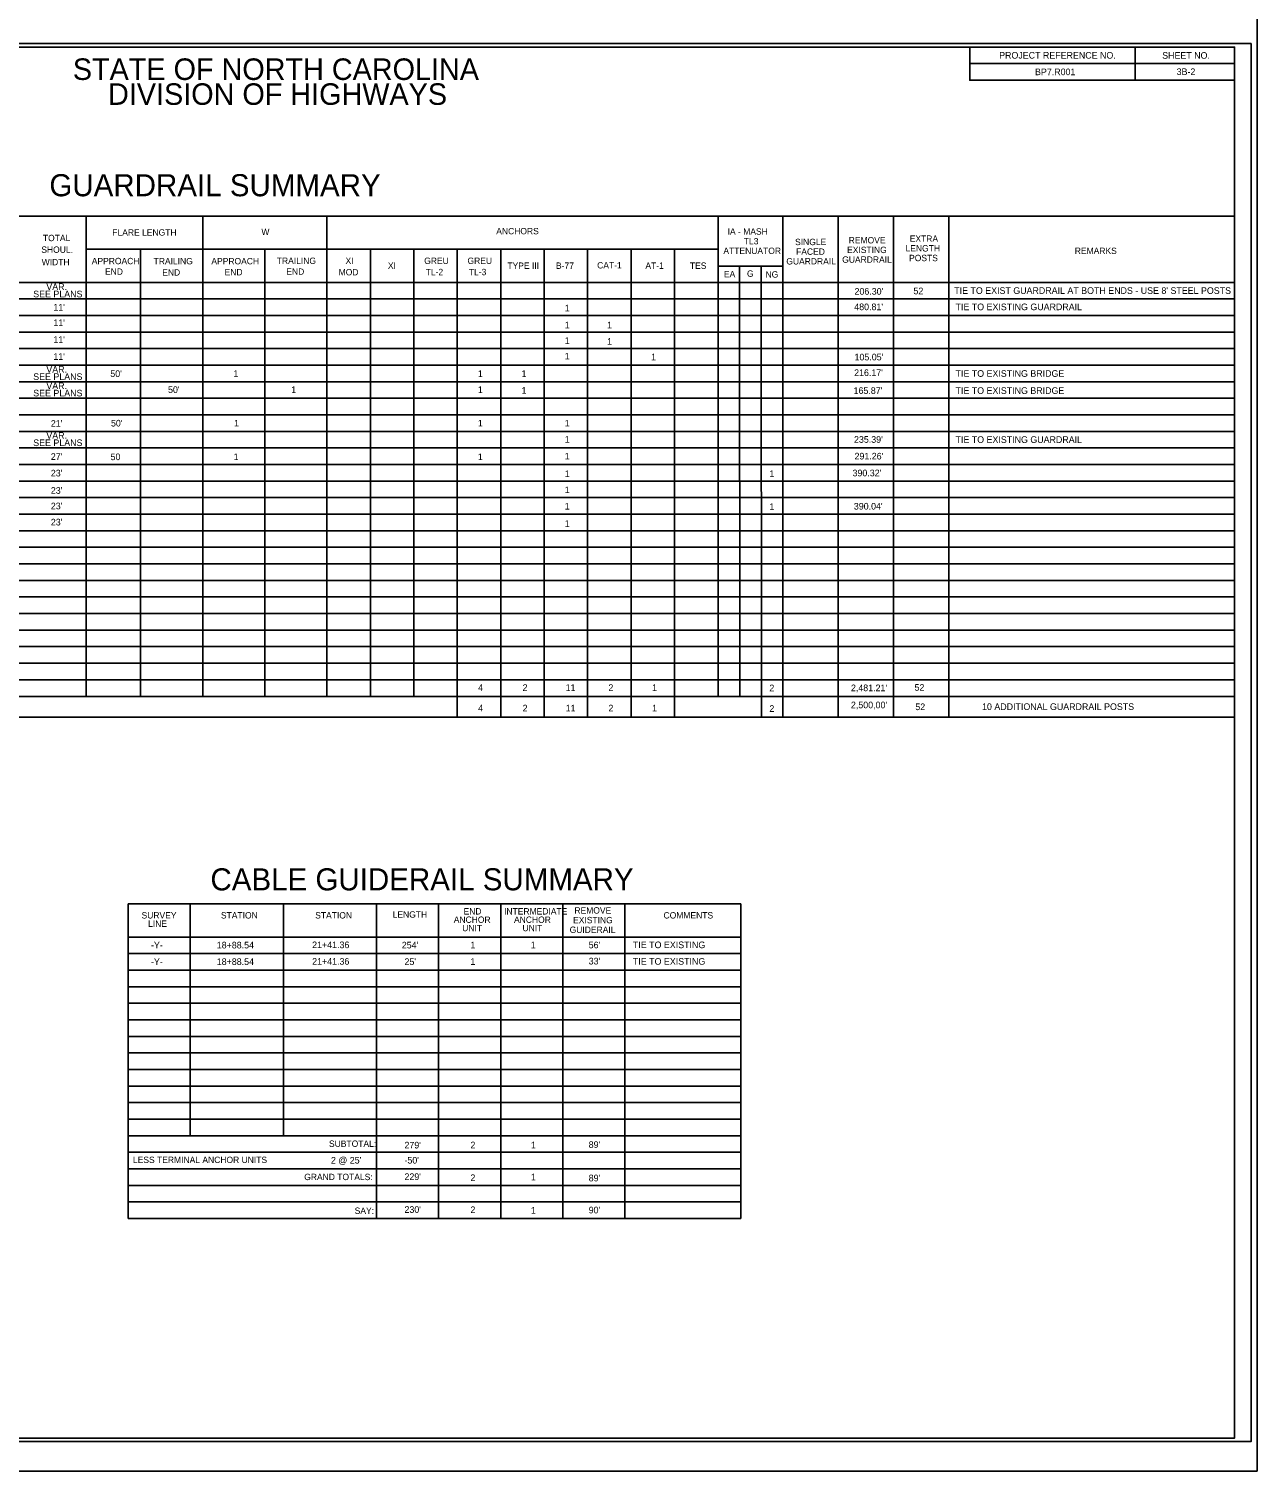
# Model space of a CAD drawing. Extents: x 1730642 to 1732326, y 538795 to 540995.
# Drawn here: x 1731398 to 1732326, y 538795 to 539884 of the extents above; entities that cross this region are included whole.
import ezdxf

# ---------------------------------------------------------------- set-up
doc = ezdxf.new("R2010")
doc.units = 0
for name, color, linetype in [('Default', 7, 'Continuous'), ('Old_Level_40', 7, 'Continuous'), ('Old_Level_44', 7, 'Continuous'), ('Sheet Cutting Line CELL', 7, 'Continuous'), ('Sheet Data Field CELL', 7, 'Continuous'), ('Sheet Pipe Summary CELL', 7, 'Continuous'), ('Sheet Pipe Summary Grid CELL', 7, 'Continuous'), ('Sheet Summary Combination CELL', 7, 'Continuous'), ('Sheet Summary Earthwork CELL', 7, 'Continuous')]:
    doc.layers.add(name, color=color, linetype=linetype)

msp = doc.modelspace()

# ---------------------------------------------------------------- linework, layer by layer
at = {"layer": 'Old_Level_40'}
for p, q in [((1732233.5, 539870.4), (1732233.5, 539845.4)), ((1732108.5, 539857.9), (1732308.5, 539857.9)), ((1732108.5, 539845.4), (1732308.5, 539845.4)), ((1731614.3, 539223.6), (1731614.3, 539223.6)), ((1731620.6, 539223.5), (1731620.6, 539223.5)), ((1731629.6, 539223.7), (1731629.6, 539223.7)), ((1731635.2, 539223.6), (1731635.2, 539223.6))]:
    msp.add_line(p, q, dxfattribs=at)
for points in [[(1732308.5, 539870.4), (1730808.5, 539870.4), (1730808.5, 538820.4), (1732308.5, 538820.4)], [(1732108.5, 539870.4), (1732308.5, 539870.4), (1732308.5, 539845.4), (1732108.5, 539845.4)]]:
    msp.add_lwpolyline(points, close=True, dxfattribs=at)
at = {"layer": 'Old_Level_44'}
for p, q in [((1730808.5, 539742.8), (1732308.5, 539742.8)), ((1731441.3, 539742.8), (1731441.3, 539380.3)), ((1731529.4, 539742.8), (1731529.4, 539380.3)), ((1731623.2, 539742.8), (1731623.2, 539380.3)), ((1731918.5, 539742.8), (1731918.5, 539380.3)), ((1731967.3, 539742.8), (1731967.3, 539364.7)), ((1732009.1, 539742.8), (1732009.1, 539364.7)), ((1732050.9, 539742.8), (1732050.9, 539364.7)), ((1732092.8, 539742.8), (1732092.8, 539364.7)), ((1731918.5, 539717.8), (1731441.3, 539717.8)), ((1731482.5, 539717.8), (1731482.5, 539380.3)), ((1731576.3, 539717.8), (1731576.3, 539380.3)), ((1731656, 539717.8), (1731656, 539380.3)), ((1731688.8, 539717.8), (1731688.8, 539380.3)), ((1731721.6, 539717.8), (1731721.6, 539364.7)), ((1731754.4, 539717.8), (1731754.4, 539364.7)), ((1731787.2, 539717.8), (1731787.2, 539364.7)), ((1731820, 539717.8), (1731820, 539364.7)), ((1731852.9, 539717.8), (1731852.9, 539364.7)), ((1731885.7, 539717.8), (1731885.7, 539364.7)), ((1731918.5, 539705), (1731967.1, 539705)), ((1731934.7, 539705), (1731934.9, 539380.3)), ((1731951.1, 539705), (1731951.3, 539364.7)), ((1730808.5, 539692.8), (1732308.5, 539692.8)), ((1730808.5, 539680.3), (1732308.5, 539680.3)), ((1730808.5, 539667.8), (1732308.5, 539667.8)), ((1730808.5, 539655.3), (1732308.5, 539655.3)), ((1730808.5, 539642.8), (1732308.5, 539642.8)), ((1730808.5, 539630.3), (1732308.5, 539630.3)), ((1730808.5, 539617.8), (1732308.5, 539617.8)), ((1730808.5, 539605.3), (1732308.5, 539605.3)), ((1730808.5, 539592.8), (1732308.5, 539592.8)), ((1730808.5, 539580.3), (1732308.5, 539580.3)), ((1730808.5, 539567.8), (1732308.5, 539567.8)), ((1730808.5, 539555.3), (1732308.5, 539555.3)), ((1730808.5, 539542.8), (1732308.5, 539542.8)), ((1730808.5, 539530.3), (1732308.5, 539530.3)), ((1730808.5, 539517.8), (1732308.5, 539517.8)), ((1730808.5, 539505.3), (1732308.5, 539505.3)), ((1730808.5, 539492.8), (1732308.5, 539492.8)), ((1730808.5, 539480.3), (1732308.5, 539480.3)), ((1730808.5, 539467.8), (1732308.5, 539467.8)), ((1730808.5, 539455.3), (1732308.5, 539455.3)), ((1730808.5, 539442.8), (1732308.5, 539442.8)), ((1730808.5, 539430.3), (1732308.5, 539430.3)), ((1730808.5, 539417.8), (1732308.5, 539417.8)), ((1730808.5, 539405.3), (1732308.5, 539405.3)), ((1730808.5, 539392.8), (1732308.5, 539392.8)), ((1730808.5, 539380.3), (1732308.5, 539380.3)), ((1730808.5, 539364.7), (1732308.5, 539364.7)), ((1731473.1, 539223.6), (1731935.7, 539223.6)), ((1731473.1, 539223.6), (1731473.1, 538986.1)), ((1731520, 539223.6), (1731520, 539048.6)), ((1731590.3, 539223.6), (1731590.3, 539048.6)), ((1731660.6, 539223.6), (1731660.6, 538986.1)), ((1731707.5, 539223.6), (1731707.5, 538986.1)), ((1731754.4, 539223.6), (1731754.4, 538986.1)), ((1731801.3, 539223.6), (1731801.3, 538986.1)), ((1731848.2, 539223.6), (1731848.2, 538986.1)), ((1731935.7, 539223.6), (1731935.7, 538986.1)), ((1731473.1, 539198.6), (1731935.7, 539198.6)), ((1731473.1, 539186.1), (1731935.7, 539186.1)), ((1731473.1, 539173.6), (1731935.7, 539173.6)), ((1731473.1, 539161.1), (1731935.7, 539161.1)), ((1731473.1, 539148.6), (1731935.7, 539148.6)), ((1731473.1, 539136.1), (1731935.7, 539136.1)), ((1731473.1, 539123.6), (1731935.7, 539123.6)), ((1731473.1, 539111.1), (1731935.7, 539111.1)), ((1731473.1, 539098.6), (1731935.7, 539098.6)), ((1731473.1, 539086.1), (1731935.7, 539086.1)), ((1731473.1, 539073.6), (1731935.7, 539073.6)), ((1731473.1, 539061.1), (1731935.7, 539061.1)), ((1731473.1, 539048.6), (1731935.7, 539048.6)), ((1731473.1, 539036.1), (1731935.7, 539036.1)), ((1731473.1, 539023.6), (1731935.7, 539023.6)), ((1731473.1, 539011.1), (1731935.7, 539011.1)), ((1731473.1, 538998.6), (1731935.7, 538998.6)), ((1731473.1, 538986.1), (1731935.7, 538986.1))]:
    msp.add_line(p, q, dxfattribs=at)
at = {"layer": 'Sheet Cutting Line CELL'}
msp.add_lwpolyline([(1730641.5, 539895.4), (1732325.5, 539895.4), (1732325.5, 538795.4), (1730641.5, 538795.4)], close=True, dxfattribs=at)
at = {"layer": 'Sheet Pipe Summary CELL'}
msp.add_lwpolyline([(1732321, 539873), (1730654.5, 539873), (1730654.5, 538817.9), (1732321, 538817.9)], close=True, dxfattribs=at)
at = {"layer": 'Sheet Pipe Summary Grid CELL'}
msp.add_lwpolyline([(1732325.5, 539895.4), (1730641.5, 539895.4), (1730641.5, 538795.4), (1732325.5, 538795.4)], close=True, dxfattribs=at)
at = {"layer": 'Sheet Summary Earthwork CELL'}
msp.add_line((1730641.5, 538795.4), (1732325.5, 538795.4), dxfattribs=at)

# ---------------------------------------------------------------- texts
at = {"layer": 'Default'}
for s, p in [('3B-2', (1732264.7, 539849.3)), ('SEE PLANS', (1731401.4, 539681.5)), ('VAR.', (1731411.3, 539687)), ("206.30'", (1732021.5, 539683.5)), ('52', (1732066, 539683.8)), ("TIE TO EXIST GUARDRAIL AT BOTH ENDS - USE 8' STEEL POSTS", (1732096.8, 539684.1)), ("11'", (1731416.6, 539671.5)), ('1', (1731802.7, 539670.9)), ("480.81'", (1732021.3, 539671.8)), ('TIE TO EXISTING GUARDRAIL ', (1732097.8, 539671.8)), ("11'", (1731416.6, 539659.8)), ('1', (1731802.7, 539658.1)), ('1', (1731834.7, 539658.1)), ("11'", (1731416.6, 539647.1)), ('1', (1731802.7, 539646.3)), ('1', (1731834.7, 539645.7)), ('VAR.', (1731411.3, 539624.6)), ("11'", (1731416.6, 539634.3)), ('1', (1731802.7, 539634.6)), ('1', (1731867.9, 539634)), ("105.05'", (1732021.5, 539633.9)), ('SEE PLANS', (1731401.4, 539619.1)), ("50'", (1731459.6, 539621.4)), ('1', (1731552.5, 539621.4)), ('1', (1731737.1, 539621.4)), ('1', (1731770.1, 539621.4)), ("216.17'", (1732021.2, 539622.1)), ('TIE TO EXISTING BRIDGE', (1732097.8, 539621.5)), ('SEE PLANS', (1731401.4, 539606.7)), ('VAR.', (1731411.3, 539612.2)), ("50'", (1731503.2, 539609.3)), ('1', (1731596.2, 539609.3)), ('1', (1731737.1, 539609.3)), ('1', (1731770.1, 539608.7)), ("165.87'", (1732020.8, 539608.6)), ('TIE TO EXISTING BRIDGE', (1732097.8, 539608.6)), ("21'", (1731414.7, 539583.8)), ("50'", (1731460.1, 539584)), ('1', (1731553, 539584)), ('1', (1731737.1, 539584)), ('1', (1731802.7, 539584)), ('VAR.', (1731411.3, 539574.7)), ('1', (1731802.7, 539571.8)), ("235.39'", (1732021.1, 539571.7)), ('TIE TO EXISTING GUARDRAIL ', (1732097.8, 539571.6)), ('SEE PLANS', (1731401.4, 539569.2)), ("27'", (1731414.7, 539558.8)), ('50', (1731459.8, 539558.6)), ('1', (1731552.7, 539558.6)), ('1', (1731737.1, 539558.6)), ('1', (1731802.7, 539559.1)), ("291.26'", (1732021.5, 539559.1)), ("23'", (1731414.7, 539546.3)), ('1', (1731802.7, 539545.8)), ('1', (1731957.2, 539545.8)), ("390.32'", (1732020, 539546.4)), ("23'", (1731414.7, 539533.2)), ('1', (1731802.7, 539533.7)), ("23'", (1731414.7, 539521.5)), ('1', (1731802.7, 539521.3)), ('1', (1731957.2, 539520.9)), ("390.04'", (1732021, 539521.3)), ("23'", (1731414.7, 539509.3)), ('1', (1731802.7, 539508.2)), ('2', (1731957.2, 539384.1)), ("2,481.21'", (1732018.8, 539384.2)), ('52', (1732066.8, 539384.5)), ('2', (1731957.2, 539368.6)), ("2,500,00'", (1732018.8, 539371.3)), ('52', (1732067.4, 539369.9)), ('10 ADDITIONAL GUARDRAIL POSTS', (1732117.8, 539370)), ('-Y-', (1731490.3, 539190)), ('18+88.54', (1731540, 539190)), ('21+41.36', (1731612, 539190.2)), ("254'", (1731679.7, 539190)), ('1', (1731731.5, 539190.1)), ('1', (1731777, 539190.1)), ("56'", (1731820.8, 539190.1)), ('TIE TO EXISTING', (1731854.2, 539190.2)), ('-Y-', (1731490.3, 539177.5)), ('18+88.54', (1731540, 539177.5)), ('21+41.36', (1731612, 539177.7)), ("25'", (1731681.7, 539177.5)), ('1', (1731731.5, 539177.6)), ("33'", (1731820.8, 539177.9)), ('TIE TO EXISTING', (1731854.2, 539177.7)), ("279'", (1731681.7, 539039)), ('2', (1731731.5, 539039.1)), ('1', (1731777.2, 539039.1)), ("89'", (1731820.8, 539039.4)), ("2 @ 25'", (1731626.2, 539027.6)), ("-50'", (1731681.7, 539027.6)), ("229'", (1731681.7, 539015.2)), ('1', (1731777.2, 539015)), ('2', (1731731.5, 539014.4)), ("89'", (1731820.8, 539014.2)), ("230'", (1731681.7, 538990.4)), ('2', (1731731.5, 538990.2)), ('1', (1731777.2, 538989.8)), ("90'", (1731820.8, 538990))]:
    msp.add_text(s, height=5, dxfattribs=at).set_placement(p)
at = {"layer": 'Old_Level_40'}
for s, height, p in [('STATE OF NORTH CAROLINA', 16.25, (1731431.3, 539845.6)), ('PROJECT REFERENCE NO.', 5, (1732130.7, 539861.7)), ('SHEET NO.', 5, (1732253.8, 539861.6)), ('DIVISION OF HIGHWAYS', 16.25, (1731457.9, 539826.8)), ('GUARDRAIL SUMMARY', 16.667, (1731413.6, 539757.8)), ('TOTAL', 4.8, (1731408.7, 539723.9)), ('FLARE LENGTH', 4.8, (1731461.1, 539728.1)), ('W', 4.8, (1731573.7, 539728.5)), ('ANCHORS', 4.8, (1731751, 539729.1)), ('IA - MASH', 4.8, (1731925.7, 539728.8)), ('EXTRA', 4.8, (1732063.2, 539723.4)), ('SHOUL.', 4.8, (1731407.5, 539715.1)), ('ATTENUATOR', 4.8, (1731922.5, 539714.2)), ('TL3', 4.8, (1731937.9, 539721.5)), ('SINGLE', 4.8, (1731976.6, 539720.9)), ('FACED', 4.8, (1731977.4, 539713.6)), ('EXISTING', 4.8, (1732015.9, 539714.9)), ('REMOVE', 4.8, (1732017.1, 539722.2)), ('LENGTH', 4.8, (1732060, 539716.1)), ('REMARKS', 4.8, (1732187.8, 539714.2)), ('WIDTH', 4.8, (1731407.8, 539705.7)), ('APPROACH', 4.8, (1731445.6, 539706.5)), ('TRAILING', 4.8, (1731492.3, 539706.4)), ('APPROACH', 4.8, (1731535.9, 539706.4)), ('TRAILING', 4.8, (1731585.3, 539706.7)), ('XI', 4.8, (1731637.2, 539706.7)), ('XI', 4.8, (1731669.2, 539703)), ('GREU', 4.8, (1731696.6, 539706.7)), ('GREU', 4.8, (1731729.3, 539706.7)), ('TYPE III', 4.8, (1731759.4, 539703)), ('B-77', 4.8, (1731796.1, 539703)), ('CAT-1', 4.8, (1731827.2, 539703.3)), ('AT-1', 4.8, (1731863.6, 539703)), ('TES', 4.8, (1731897.2, 539703)), ('GUARDRAIL', 4.8, (1731970, 539706.3)), ('GUARDRAIL', 4.8, (1732012.2, 539707.6)), ('POSTS', 4.8, (1732062.7, 539708.8)), ('END', 4.8, (1731455.6, 539698.5)), ('END', 4.8, (1731498.8, 539697.9)), ('END', 4.8, (1731545.9, 539698.1)), ('END', 4.8, (1731592.5, 539698.5)), ('MOD', 4.8, (1731632, 539698.1)), ('TL-2', 4.8, (1731697.7, 539698.2)), ('TL-3', 4.8, (1731730.3, 539698.2)), ('EA', 4.8, (1731922.9, 539696.6)), ('G', 4.8, (1731940.3, 539697)), ('NG', 4.8, (1731954.3, 539696.4)), ('SURVEY', 4.8, (1731483.2, 539212.6)), ('STATION', 4.8, (1731543.1, 539212.6)), ('STATION', 4.8, (1731614.3, 539212.6)), ('LENGTH', 4.8, (1731672.8, 539213.2)), ('END', 4.8, (1731726.3, 539215.6)), ('INTERMEDIATE', 4.8, (1731756.9, 539215.6)), ('REMOVE', 4.8, (1731810, 539216.3)), ('COMMENTS', 4.8, (1731877.3, 539212.6)), ('LINE', 4.8, (1731488.1, 539206.3)), ('ANCHOR', 4.8, (1731718.9, 539209.3)), ('UNIT', 4.8, (1731725.3, 539203)), ('ANCHOR', 4.8, (1731764.4, 539209.3)), ('UNIT', 4.8, (1731770.8, 539203)), ('GUIDERAIL', 4.8, (1731806.4, 539201.7)), ('EXISTING', 4.8, (1731809, 539209)), ('SUBTOTAL:', 4.8, (1731624.7, 539040.2)), ('LESS TERMINAL ANCHOR UNITS', 4.8, (1731476.7, 539028)), ('GRAND TOTALS:', 4.8, (1731606, 539015.1)), ('SAY:', 4.8, (1731644.1, 538989.6))]:
    msp.add_text(s, height=height, dxfattribs=at).set_placement(p)
msp.add_text('CABLE GUIDERAIL SUMMARY', height=16.667, rotation=0.0119, dxfattribs=at).set_placement((1731535.2, 539233.8))
at = {"layer": 'Sheet Data Field CELL'}
for s, p in [('4', (1731737.3, 539384.4)), ('2', (1731770.9, 539384.4)), ('11', (1731803.4, 539384.4)), ('2', (1731835.7, 539384.4)), ('1', (1731868.7, 539384.4)), ('4', (1731737.3, 539368.9)), ('2', (1731770.9, 539368.9)), ('11', (1731803.4, 539368.9)), ('2', (1731835.7, 539368.9)), ('1', (1731868.7, 539368.9))]:
    msp.add_text(s, height=5, dxfattribs=at).set_placement(p)
at = {"layer": 'Sheet Summary Combination CELL'}
msp.add_text('BP7.R001', height=5, dxfattribs=at).set_placement((1732157.8, 539849.2))

doc.saveas('drawing.dxf')
